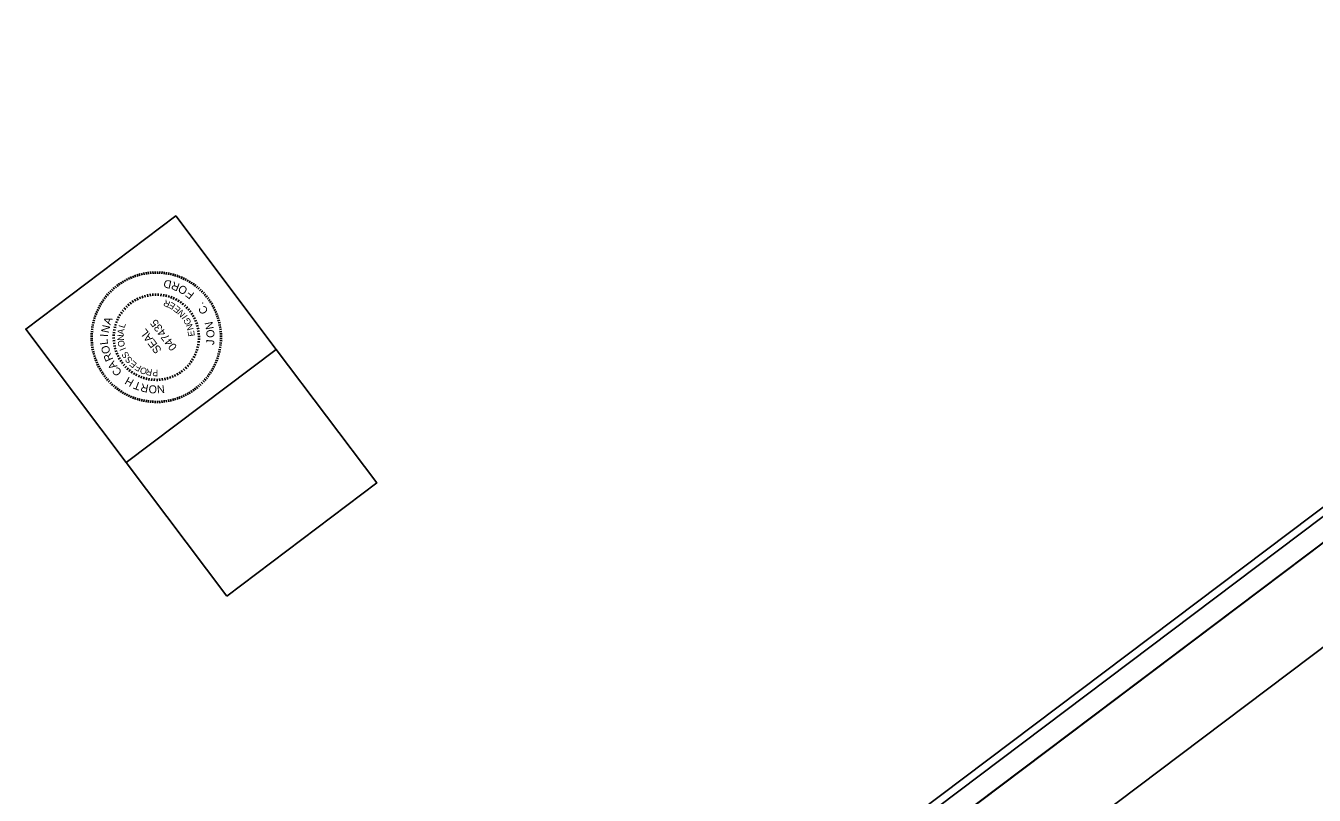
# Model space of a CAD drawing. Extents: x 1262749 to 1264921, y 774795 to 776798.
# Drawn here: x 1262749 to 1263520, y 776338 to 776798 of the extents above; entities that cross this region are included whole.
import ezdxf

# ---------------------------------------------------------------- set-up
doc = ezdxf.new("R2010")
doc.units = 0
for name, color, linetype in [('Sheet Border Standard 30in CELL', 7, 'Continuous'), ('Sheet Layout Plan Border', 7, 'Continuous'), ('Sheet PE Seal Cell', 7, 'Continuous'), ('Sheet Plan CELL', 7, 'Continuous'), ('Sheet Plan Layout CELL', 7, 'Continuous'), ('Sheet Plot Border Inside CELL', 7, 'Continuous'), ('Sheet Plot Border Outside CELL', 7, 'Continuous')]:
    doc.layers.add(name, color=color, linetype=linetype)

msp = doc.modelspace()

# ---------------------------------------------------------------- linework, layer by layer
at = {"layer": 'Sheet Border Standard 30in CELL'}
msp.add_line((1262809.03, 776536.91), (1262898.82, 776604.55), dxfattribs=at)
for points in [[(1262809.03, 776536.91), (1262748.88, 776616.76), (1262838.72, 776684.43), (1262898.86, 776604.58)], [(1262869.2, 776457.02), (1262809.03, 776536.91), (1262898.86, 776604.58), (1262959.04, 776524.68)]]:
    msp.add_lwpolyline(points, close=True, dxfattribs=at)
at = {"layer": 'Sheet Layout Plan Border'}
msp.add_lwpolyline([(1264772.58, 775612.83), (1263930.27, 776731.11), (1263260.5, 776226.63), (1263374.36, 776075.45), (1263205.44, 775948.22), (1263933.87, 774981.11)], close=True, dxfattribs=at)
at = {"layer": 'Sheet PE Seal Cell'}
for p, q in [((1262812.93, 776648.67), (1262813.43, 776647.36)), ((1262814.23, 776649.1), (1262814.66, 776647.8)), ((1262815.52, 776649.53), (1262815.91, 776648.22)), ((1262816.84, 776649.93), (1262817.2, 776648.58)), ((1262818.19, 776650.22), (1262818.5, 776648.91)), ((1262819.52, 776650.5), (1262819.81, 776649.16)), ((1262820.89, 776650.76), (1262821.08, 776649.4)), ((1262822.25, 776650.94), (1262822.44, 776649.59)), ((1262823.64, 776651.09), (1262823.73, 776649.71)), ((1262824.99, 776651.21), (1262825.07, 776649.83)), ((1262826.36, 776651.23), (1262826.37, 776649.85)), ((1262827.73, 776651.23), (1262827.7, 776649.84)), ((1262829.13, 776651.2), (1262829.04, 776649.81)), ((1262830.48, 776651.08), (1262830.36, 776649.73)), ((1262831.83, 776650.96), (1262831.67, 776649.58)), ((1262833.2, 776650.73), (1262833.01, 776649.39)), ((1262834.57, 776650.51), (1262834.32, 776649.17)), ((1262835.91, 776650.25), (1262835.61, 776648.89)), ((1262837.26, 776649.89), (1262836.9, 776648.54)), ((1262838.58, 776649.5), (1262838.19, 776648.19)), ((1262839.89, 776649.12), (1262839.43, 776647.81)), ((1262841.15, 776648.63), (1262840.69, 776647.33)), ((1262801.19, 776641.56), (1262802.08, 776640.54)), ((1262802.24, 776642.47), (1262803.12, 776641.38)), ((1262803.35, 776643.31), (1262804.19, 776642.19)), ((1262804.43, 776644.12), (1262805.23, 776642.98)), ((1262805.59, 776644.87), (1262806.32, 776643.74)), ((1262806.76, 776645.63), (1262807.48, 776644.44)), ((1262807.94, 776646.28), (1262808.6, 776645.11)), ((1262809.17, 776646.97), (1262809.81, 776645.72)), ((1262810.39, 776647.59), (1262810.99, 776646.3)), ((1262811.66, 776648.12), (1262812.2, 776646.86)), ((1262842.44, 776648.1), (1262841.9, 776646.85)), ((1262843.71, 776647.55), (1262843.11, 776646.27)), ((1262844.92, 776646.96), (1262844.3, 776645.72)), ((1262846.15, 776646.28), (1262845.49, 776645.11)), ((1262847.33, 776645.6), (1262846.65, 776644.43)), ((1262848.53, 776644.88), (1262847.75, 776643.7)), ((1262849.65, 776644.12), (1262848.84, 776642.96)), ((1262850.74, 776643.31), (1262849.94, 776642.22)), ((1262851.85, 776642.46), (1262850.98, 776641.4)), ((1262852.88, 776641.57), (1262851.98, 776640.53)), ((1262793.98, 776633.3), (1262795.13, 776632.56)), ((1262794.78, 776634.45), (1262795.91, 776633.68)), ((1262795.55, 776635.58), (1262796.67, 776634.74)), ((1262796.43, 776636.65), (1262797.5, 776635.79)), ((1262797.29, 776637.73), (1262798.37, 776636.79)), ((1262798.22, 776638.73), (1262799.26, 776637.76)), ((1262799.19, 776639.69), (1262800.14, 776638.73)), ((1262800.18, 776640.67), (1262801.12, 776639.66)), ((1262813.36, 776632.56), (1262812.61, 776633.72)), ((1262814.72, 776633.4), (1262814.03, 776634.56)), ((1262816.11, 776634.08), (1262815.47, 776635.34)), ((1262817.54, 776634.75), (1262816.97, 776636.05)), ((1262818.99, 776635.29), (1262818.52, 776636.63)), ((1262820.45, 776635.74), (1262820.1, 776637.08)), ((1262821.97, 776636.1), (1262821.7, 776637.51)), ((1262823.49, 776636.4), (1262823.3, 776637.76)), ((1262825.05, 776636.57), (1262824.94, 776637.98)), ((1262826.6, 776636.65), (1262826.59, 776638.01)), ((1262828.17, 776636.64), (1262828.22, 776638)), ((1262829.73, 776636.49), (1262829.89, 776637.87)), ((1262831.27, 776636.27), (1262831.5, 776637.64)), ((1262832.81, 776635.98), (1262833.13, 776637.31)), ((1262834.32, 776635.56), (1262834.72, 776636.88)), ((1262835.78, 776635.05), (1262836.24, 776636.36)), ((1262837.2, 776634.44), (1262837.8, 776635.72)), ((1262838.61, 776633.76), (1262839.27, 776635.04)), ((1262839.95, 776633.03), (1262840.69, 776634.18)), ((1262841.26, 776632.15), (1262842.08, 776633.31)), ((1262853.93, 776640.67), (1262852.96, 776639.64)), ((1262854.91, 776639.67), (1262853.95, 776638.72)), ((1262855.87, 776638.72), (1262854.85, 776637.77)), ((1262856.78, 776637.67), (1262855.74, 776636.76)), ((1262857.66, 776636.66), (1262856.58, 776635.78)), ((1262858.5, 776635.54), (1262857.39, 776634.71)), ((1262859.34, 776634.43), (1262858.2, 776633.63)), ((1262860.07, 776633.31), (1262858.9, 776632.55)), ((1262790.27, 776625.95), (1262791.53, 776625.47)), ((1262790.76, 776627.22), (1262792.04, 776626.7)), ((1262791.35, 776628.51), (1262792.56, 776627.93)), ((1262791.93, 776629.73), (1262793.18, 776629.1)), ((1262792.58, 776630.93), (1262793.79, 776630.29)), ((1262793.27, 776632.17), (1262794.46, 776631.45)), ((1262805.87, 776624.75), (1262804.68, 776625.47)), ((1262806.74, 776626.07), (1262805.59, 776626.88)), ((1262807.66, 776627.31), (1262806.57, 776628.21)), ((1262808.7, 776628.5), (1262807.62, 776629.43)), ((1262809.74, 776629.65), (1262808.78, 776630.61)), ((1262810.88, 776630.69), (1262809.97, 776631.74)), ((1262812.11, 776631.68), (1262811.28, 776632.78)), ((1262842.5, 776631.23), (1262843.37, 776632.3)), ((1262843.69, 776630.2), (1262844.66, 776631.23)), ((1262844.8, 776629.13), (1262845.83, 776630.08)), ((1262845.87, 776627.95), (1262846.92, 776628.85)), ((1262846.87, 776626.78), (1262847.98, 776627.62)), ((1262847.74, 776625.47), (1262848.88, 776626.26)), ((1262860.83, 776632.14), (1262859.64, 776631.42)), ((1262861.51, 776630.91), (1262860.33, 776630.26)), ((1262862.17, 776629.73), (1262860.91, 776629.08)), ((1262862.75, 776628.48), (1262861.5, 776627.9)), ((1262863.32, 776627.24), (1262862.05, 776626.7)), ((1262863.83, 776625.94), (1262862.56, 776625.47)), ((1262788.1, 776618.02), (1262789.5, 776617.82)), ((1262788.35, 776619.35), (1262789.72, 776619.12)), ((1262788.65, 776620.71), (1262790.01, 776620.42)), ((1262788.97, 776622.03), (1262790.32, 776621.68)), ((1262789.36, 776623.36), (1262790.67, 776622.96)), ((1262789.78, 776624.69), (1262791.09, 776624.24)), ((1262802.91, 776617.61), (1262801.55, 776617.91)), ((1262803.3, 776619.1), (1262801.99, 776619.48)), ((1262803.81, 776620.57), (1262802.51, 776621.09)), ((1262804.39, 776622.02), (1262803.14, 776622.58)), ((1262805.1, 776623.39), (1262803.86, 776624.08)), ((1262848.55, 776624.15), (1262849.78, 776624.83)), ((1262849.28, 776622.78), (1262850.57, 776623.39)), ((1262849.94, 776621.36), (1262851.21, 776621.9)), ((1262850.48, 776619.91), (1262851.82, 776620.37)), ((1262850.96, 776618.41), (1262852.28, 776618.8)), ((1262864.3, 776624.67), (1262862.96, 776624.21)), ((1262864.72, 776623.38), (1262863.37, 776622.95)), ((1262865.09, 776622.03), (1262863.77, 776621.69)), ((1262865.44, 776620.67), (1262864.1, 776620.39)), ((1262865.73, 776619.34), (1262864.36, 776619.08)), ((1262865.96, 776618.01), (1262864.59, 776617.75)), ((1262787.64, 776611.13), (1262789.05, 776611.17)), ((1262787.67, 776612.54), (1262789.02, 776612.48)), ((1262787.68, 776609.8), (1262789.07, 776609.87)), ((1262787.69, 776613.94), (1262789.08, 776613.84)), ((1262787.78, 776615.26), (1262789.17, 776615.17)), ((1262787.94, 776616.64), (1262789.32, 776616.48)), ((1262802.25, 776611.4), (1262800.85, 776611.37)), ((1262802.26, 776612.98), (1262800.87, 776613.01)), ((1262802.33, 776609.86), (1262800.91, 776609.75)), ((1262802.37, 776614.5), (1262800.99, 776614.66)), ((1262802.59, 776616.05), (1262801.22, 776616.27)), ((1262851.32, 776616.88), (1262852.71, 776617.2)), ((1262851.59, 776615.34), (1262852.96, 776615.6)), ((1262851.79, 776613.81), (1262853.14, 776613.93)), ((1262851.83, 776610.73), (1262853.22, 776610.63)), ((1262851.85, 776612.3), (1262853.22, 776612.31)), ((1262866.14, 776616.64), (1262864.79, 776616.46)), ((1262866.29, 776615.25), (1262864.94, 776615.13)), ((1262866.4, 776609.77), (1262865.01, 776609.86)), ((1262866.41, 776613.9), (1262865.02, 776613.83)), ((1262866.45, 776611.13), (1262865.06, 776611.16)), ((1262866.45, 776612.5), (1262865.08, 776612.49)), ((1262787.77, 776608.42), (1262789.18, 776608.53)), ((1262787.92, 776607.03), (1262789.31, 776607.24)), ((1262788.1, 776605.66), (1262789.49, 776605.88)), ((1262788.32, 776604.33), (1262789.73, 776604.62)), ((1262788.64, 776602.96), (1262789.99, 776603.31)), ((1262802.49, 776608.29), (1262801.13, 776608.1)), ((1262802.76, 776606.75), (1262801.38, 776606.5)), ((1262803.09, 776605.27), (1262801.78, 776604.87)), ((1262803.57, 776603.76), (1262802.27, 776603.33)), ((1262804.11, 776602.32), (1262802.85, 776601.78)), ((1262850.25, 776603.11), (1262851.58, 776602.61)), ((1262850.76, 776604.57), (1262852.07, 776604.18)), ((1262851.18, 776606.09), (1262852.5, 776605.77)), ((1262851.49, 776607.59), (1262852.86, 776607.36)), ((1262851.71, 776609.13), (1262853.06, 776609.01)), ((1262865.44, 776602.99), (1262864.08, 776603.29)), ((1262865.7, 776604.32), (1262864.37, 776604.58)), ((1262865.96, 776605.66), (1262864.59, 776605.88)), ((1262866.15, 776607), (1262864.78, 776607.22)), ((1262866.31, 776608.38), (1262864.93, 776608.54)), ((1262788.97, 776601.64), (1262790.32, 776602.01)), ((1262789.37, 776600.32), (1262790.68, 776600.72)), ((1262789.76, 776599), (1262791.09, 776599.47)), ((1262790.23, 776597.73), (1262791.54, 776598.23)), ((1262790.78, 776596.46), (1262792.04, 776597)), ((1262791.31, 776595.19), (1262792.6, 776595.8)), ((1262791.92, 776593.97), (1262793.14, 776594.59)), ((1262804.78, 776600.89), (1262803.55, 776600.27)), ((1262805.5, 776599.52), (1262804.3, 776598.8)), ((1262806.34, 776598.17), (1262805.18, 776597.41)), ((1262807.22, 776596.92), (1262806.12, 776596.09)), ((1262808.21, 776595.69), (1262807.13, 776594.82)), ((1262809.25, 776594.55), (1262808.25, 776593.55)), ((1262845.43, 776595.17), (1262846.43, 776594.24)), ((1262846.46, 776596.36), (1262847.52, 776595.49)), ((1262847.35, 776597.63), (1262848.51, 776596.82)), ((1262848.19, 776598.92), (1262849.38, 776598.21)), ((1262848.98, 776600.24), (1262850.23, 776599.63)), ((1262849.66, 776601.65), (1262850.92, 776601.1)), ((1262862.12, 776593.94), (1262860.91, 776594.6)), ((1262862.74, 776595.19), (1262861.49, 776595.75)), ((1262863.3, 776596.45), (1262862.05, 776597)), ((1262863.85, 776597.71), (1262862.52, 776598.21)), ((1262864.31, 776599.01), (1262863, 776599.47)), ((1262864.73, 776600.29), (1262863.38, 776600.71)), ((1262865.09, 776601.63), (1262863.74, 776601.99)), ((1262792.58, 776592.72), (1262793.79, 776593.41)), ((1262793.26, 776591.57), (1262794.46, 776592.28)), ((1262793.99, 776590.37), (1262795.16, 776591.13)), ((1262794.75, 776589.27), (1262795.89, 776590.07)), ((1262795.55, 776588.13), (1262796.66, 776588.97)), ((1262796.43, 776587.04), (1262797.51, 776587.92)), ((1262797.27, 776586.01), (1262798.32, 776586.92)), ((1262810.36, 776593.47), (1262809.46, 776592.43)), ((1262811.55, 776592.44), (1262810.68, 776591.37)), ((1262812.79, 776591.52), (1262812.02, 776590.39)), ((1262814.1, 776590.64), (1262813.36, 776589.49)), ((1262815.47, 776589.88), (1262814.82, 776588.66)), ((1262816.88, 776589.2), (1262816.29, 776587.98)), ((1262818.34, 776588.61), (1262817.81, 776587.32)), ((1262819.77, 776588.14), (1262819.35, 776586.8)), ((1262821.29, 776587.72), (1262820.96, 776586.33)), ((1262822.81, 776587.36), (1262822.55, 776586.03)), ((1262824.36, 776587.15), (1262824.2, 776585.77)), ((1262825.92, 776587.07), (1262825.83, 776585.68)), ((1262827.46, 776587.02), (1262827.47, 776585.65)), ((1262829.01, 776587.12), (1262829.15, 776585.72)), ((1262830.56, 776587.27), (1262830.75, 776585.91)), ((1262832.11, 776587.54), (1262832.39, 776586.19)), ((1262833.6, 776587.93), (1262833.96, 776586.59)), ((1262835.11, 776588.41), (1262835.57, 776587.08)), ((1262836.58, 776588.92), (1262837.12, 776587.65)), ((1262838.01, 776589.58), (1262838.58, 776588.33)), ((1262839.37, 776590.31), (1262840.06, 776589.08)), ((1262840.69, 776591.12), (1262841.44, 776589.95)), ((1262841.98, 776592.03), (1262842.81, 776590.92)), ((1262843.17, 776592.98), (1262844.08, 776591.94)), ((1262844.35, 776594.06), (1262845.31, 776593.03)), ((1262856.8, 776585.97), (1262855.73, 776586.91)), ((1262857.66, 776587.05), (1262856.6, 776587.92)), ((1262858.54, 776588.12), (1262857.42, 776588.96)), ((1262859.31, 776589.25), (1262858.18, 776590.02)), ((1262860.08, 776590.37), (1262858.92, 776591.11)), ((1262860.83, 776591.53), (1262859.63, 776592.25)), ((1262861.5, 776592.71), (1262860.3, 776593.41)), ((1262798.22, 776584.98), (1262799.24, 776585.93)), ((1262799.17, 776583.96), (1262800.17, 776584.94)), ((1262800.17, 776583.03), (1262801.09, 776584.03)), ((1262801.17, 776582.1), (1262802.11, 776583.17)), ((1262802.24, 776581.24), (1262803.11, 776582.3)), ((1262803.31, 776580.36), (1262804.16, 776581.48)), ((1262804.4, 776579.56), (1262805.22, 776580.72)), ((1262805.57, 776578.82), (1262806.31, 776579.97)), ((1262806.72, 776578.07), (1262807.45, 776579.27)), ((1262847.33, 776578.07), (1262846.61, 776579.26)), ((1262848.49, 776578.76), (1262847.74, 776579.92)), ((1262849.63, 776579.56), (1262848.83, 776580.7)), ((1262850.77, 776580.36), (1262849.93, 776581.47)), ((1262851.81, 776581.2), (1262850.94, 776582.29)), ((1262852.89, 776582.07), (1262851.98, 776583.12)), ((1262853.92, 776583.03), (1262852.97, 776584.05)), ((1262854.89, 776583.95), (1262853.92, 776584.94)), ((1262855.87, 776584.97), (1262854.87, 776585.9)), ((1262807.93, 776577.36), (1262808.61, 776578.59)), ((1262809.13, 776576.71), (1262809.79, 776577.98)), ((1262810.35, 776576.12), (1262810.97, 776577.37)), ((1262811.61, 776575.57), (1262812.2, 776576.85)), ((1262812.9, 776575.04), (1262813.43, 776576.34)), ((1262814.21, 776574.58), (1262814.66, 776575.9)), ((1262815.5, 776574.13), (1262815.93, 776575.48)), ((1262816.86, 776573.78), (1262817.18, 776575.09)), ((1262818.19, 776573.45), (1262818.48, 776574.81)), ((1262819.51, 776573.13), (1262819.77, 776574.53)), ((1262820.88, 776572.9), (1262821.08, 776574.31)), ((1262822.22, 776572.71), (1262822.42, 776574.12)), ((1262823.57, 776572.59), (1262823.73, 776573.97)), ((1262824.96, 776572.5), (1262825.05, 776573.89)), ((1262826.33, 776572.44), (1262826.35, 776573.84)), ((1262827.73, 776572.41), (1262827.68, 776573.82)), ((1262829.1, 776572.49), (1262829.03, 776573.87)), ((1262830.48, 776572.57), (1262830.33, 776573.96)), ((1262831.8, 776572.73), (1262831.66, 776574.11)), ((1262833.21, 776572.94), (1262832.98, 776574.27)), ((1262834.54, 776573.17), (1262834.28, 776574.54)), ((1262835.9, 776573.42), (1262835.59, 776574.8)), ((1262837.25, 776573.77), (1262836.89, 776575.12)), ((1262838.54, 776574.15), (1262838.14, 776575.46)), ((1262839.86, 776574.6), (1262839.43, 776575.9)), ((1262841.16, 776575.03), (1262840.66, 776576.34)), ((1262842.43, 776575.58), (1262841.89, 776576.84)), ((1262843.7, 776576.11), (1262843.1, 776577.4)), ((1262844.92, 776576.73), (1262844.31, 776577.95)), ((1262846.14, 776577.35), (1262845.45, 776578.57))]:
    msp.add_line(p, q, dxfattribs=at)
at = {"layer": 'Sheet Plan CELL'}
msp.add_lwpolyline([(1263061.47, 776139.35), (1263963.95, 774941.17), (1264802.66, 775572.89), (1263900.19, 776771.05)], close=True, dxfattribs=at)
at = {"layer": 'Sheet Plan Layout CELL'}
msp.add_lwpolyline([(1263963.99, 774941.16), (1264802.66, 775572.89), (1263900.2, 776771.04), (1263230.42, 776266.56), (1263374.36, 776075.45), (1263205.44, 775948.22)], close=True, dxfattribs=at)
at = {"layer": 'Sheet Plot Border Inside CELL'}
msp.add_lwpolyline([(1264897.01, 775451.8), (1263894.68, 776782.53), (1263051.98, 776147.82), (1264054.31, 774817.07)], close=True, dxfattribs=at)
at = {"layer": 'Sheet Plot Border Outside CELL'}
msp.add_lwpolyline([(1264920.81, 775453.45), (1263907.95, 776798.18), (1263033.3, 776139.38), (1264046.16, 774794.65)], close=True, dxfattribs=at)

# ---------------------------------------------------------------- texts
at = {"layer": 'Sheet PE Seal Cell'}
for s, height, rotation, p in [('D', 4.79, 167.48424, (1262836.51, 776645.44)), ('R', 4.79, 158.85259, (1262841.45, 776643.64)), ('O', 4.79, 149.93322, (1262846.2, 776641.02)), ('R', 3.88, 156.6864, (1262835.77, 776633)), ('E', 3.88, 148.38436, (1262838.83, 776631.34)), ('F', 4.79, 141.73315, (1262850.16, 776637.99)), ('E', 3.88, 140.08232, (1262841.97, 776628.84)), ('N', 3.88, 131.78028, (1262844.73, 776625.88)), ('C', 4.79, 119.50665, (1262858.33, 776627.3)), ('.', 4.79, 128.1383, (1262855.66, 776631.82)), ('N', 4.79, 78.00855, (1262798.55, 776614.09)), ('A', 4.79, 68.97853, (1262799.51, 776618.87)), ('L', 3.88, 72.75389, (1262807.97, 776617.03)), ('047435', 4.791, 126.98742, (1262839.71, 776605.99)), ('I', 3.88, 123.47824, (1262845.99, 776624.37)), ('G', 3.88, 115.1762, (1262848.22, 776620.3)), ('N', 3.88, 106.87415, (1262849.48, 776616.63)), ('N', 4.79, 101.73984, (1262861.56, 776617.02)), ('L', 4.79, 96.0686, (1262798.14, 776607.54)), ('I', 4.79, 87.03858, (1262798.12, 776611.95)), ('N', 3.88, 92.17155, (1262807.67, 776609.86)), ('A', 3.88, 82.46272, (1262807.57, 776613.26)), ('O', 3.88, 101.88039, (1262808.35, 776606.41)), ('SEAL', 4.791, 126.98742, (1262830.49, 776604.29)), ('E', 3.88, 98.57211, (1262850.11, 776612.6)), ('O', 4.79, 92.82047, (1262861.94, 776611.61)), ('J', 4.79, 85.33971, (1262861.61, 776607.07)), ('O', 4.79, 105.09863, (1262799.67, 776602.57)), ('R', 4.79, 114.12865, (1262801.35, 776598.67)), ('I', 3.88, 111.58922, (1262808.97, 776604.72)), ('S', 3.88, 121.29805, (1262811.11, 776600.68)), ('A', 4.79, 123.15868, (1262803.91, 776594.55)), ('S', 3.88, 131.00688, (1262813.18, 776598.17)), ('E', 3.88, 140.71571, (1262815.69, 776596.04)), ('F', 3.88, 150.42454, (1262818.5, 776594.38)), ('C', 4.79, 132.1887, (1262806.8, 776591.19)), ('H', 4.79, 150.24875, (1262814.07, 776586.07)), ('O', 3.88, 160.13337, (1262821.91, 776592.87)), ('R', 3.88, 169.8422, (1262824.84, 776592.49)), ('P', 3.88, 179.55104, (1262828.14, 776592.4)), ('T', 4.79, 159.27878, (1262818.25, 776584.35)), ('R', 4.79, 168.3088, (1262822.69, 776583.31)), ('O', 4.79, 177.33883, (1262827.52, 776582.94)), ('N', 4.79, 186.36885, (1262831.77, 776583.38))]:
    msp.add_text(s, height=height, rotation=rotation, dxfattribs=at).set_placement(p)

doc.saveas('drawing.dxf')
